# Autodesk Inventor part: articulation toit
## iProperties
Created: 2009-03
Part Number: articulation toit
Document SubType Name: Modeling
Designer: Ordi1
Author: Ordi1
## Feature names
1. Extrusion1
2. Perçage1 [Hole]
3. Extrusion2
4. Chanfrein1 [Chamfer]
